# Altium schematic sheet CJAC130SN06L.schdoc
size 127 x 101 mm
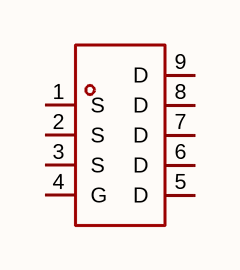
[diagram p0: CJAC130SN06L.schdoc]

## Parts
Q?  cjac130sn06l  [PDFN-8_L5.8-W5.0-P1.27-LS6.0-BL]  (value not drawn)

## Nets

Not connected (* = marked no-connect by the designer): Q? 1(S) 2(S) 3(S) 4(G) 5(D) 6(D) 7(D) 8(D) 9(D)

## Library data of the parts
Q? = cjac130sn06l: 数量:1个N沟道;漏源电压(Vdss):60V;连续漏极电流(Id):130A;导通电阻(RDS(on)):3.5mΩ@4.5V;耗散功率(Pd):130W;阈值电压(Vgs(th)):1.6V;; Manufacturer: CJ(江苏长电/长晶); AddInBom: yes; ModelId: 64dd0a0ad16f4146a485008a6fd3b168; ModelTransform: 193.7004,238.189,0,0,0,0,0,0,0; Number: 1个N沟道; Drain to Source Voltage: 60V; Current - Continuous Drain(Id): 130A; Pd - Power Dissipation: 130W; Gate Threshold Voltage (Vgs(th)): 1.6V; Gate Charge(Qg): 66.4nC@10V; Input Capacitance(Ciss): 3.56nF; Reverse Transfer Capacitance (Crss@Vds): 82pF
